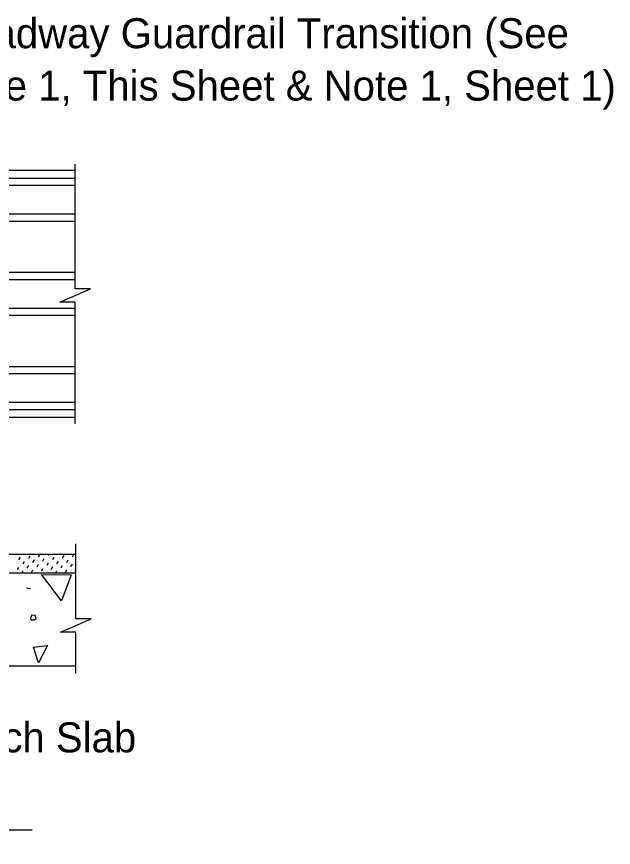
# Model space of a CAD drawing. Extents: x 2.6 to 35.7, y 1.7 to 23.4.
# Drawn here: x 17.6 to 21.61, y 5.94 to 11.53 of the extents above; entities that cross this region are included whole.
import ezdxf

# ---------------------------------------------------------------- set-up
doc = ezdxf.new("R2010")
doc.units = 0
for name, color, linetype in [('Dimension', 7, 'Continuous'), ('Miscellaneous', 7, 'Continuous'), ('TextStructures', 7, 'Continuous'), ('TrafBarrierConc', 7, 'Continuous')]:
    doc.layers.add(name, color=color, linetype=linetype)

msp = doc.modelspace()

# ---------------------------------------------------------------- linework, layer by layer
at = {"layer": 'Dimension'}
for points in [[(17.9936, 8.7897), (17.9936, 9.6071), (17.8903, 9.6071), (17.9936, 9.6521), (18.0969, 9.6971), (17.9936, 9.6971), (17.9936, 10.534)], [(17.9987, 7.1121), (17.9987, 7.389), (17.8953, 7.389), (17.9987, 7.434), (18.102, 7.479), (17.9987, 7.479), (17.9987, 7.9835)], [(17.7044, 6.0586), (14.2297, 6.0586), (14.2297, 5.9424), (14.1304, 6.1674), (14.1304, 6.0586), (12.6311, 6.0586)]]:
    msp.add_lwpolyline(points, dxfattribs=at)
at = {"layer": 'Miscellaneous'}
for p, q in [((10.4769, 10.4934), (17.9962, 10.4934)), ((11.1345, 10.4413), (17.9962, 10.4413)), ((11.1357, 10.393), (17.9962, 10.393)), ((11.1404, 10.2002), (17.9962, 10.2002)), ((11.1416, 10.152), (17.9962, 10.152)), ((11.1381, 9.808), (17.9962, 9.808)), ((11.1369, 9.7598), (17.9962, 9.7598)), ((11.1321, 9.567), (17.9962, 9.567)), ((11.1309, 9.5189), (17.9962, 9.5189)), ((11.1416, 9.1749), (17.9962, 9.1749)), ((11.1404, 9.1267), (17.9962, 9.1267)), ((11.1345, 8.8856), (17.9962, 8.8856)), ((11.1357, 8.9339), (17.9962, 8.9339)), ((10.4769, 8.8333), (17.9962, 8.8333)), ((17.6155, 7.876), (17.6252, 7.8928)), ((17.6818, 7.8857), (17.6915, 7.9025)), ((17.71, 7.8574), (17.7198, 7.8742)), ((17.7481, 7.8954), (17.7578, 7.9122)), ((17.7763, 7.8672), (17.7861, 7.8839)), ((17.8143, 7.9052), (17.8191, 7.9134)), ((17.8426, 7.8769), (17.8524, 7.8937)), ((17.9089, 7.8866), (17.9186, 7.9034)), ((17.9372, 7.8583), (17.9469, 7.8751)), ((17.9752, 7.8963), (17.9849, 7.9131)), ((17.6057, 7.8097), (17.6155, 7.8265)), ((17.6438, 7.8477), (17.6535, 7.8645)), ((17.672, 7.8194), (17.6818, 7.8362)), ((17.7383, 7.8291), (17.7481, 7.8459)), ((17.8046, 7.8389), (17.8143, 7.8557)), ((17.8329, 7.8106), (17.8426, 7.8274)), ((17.8709, 7.8486), (17.8806, 7.8654)), ((17.8992, 7.8203), (17.9089, 7.8371)), ((17.9655, 7.83), (17.9752, 7.8468)), ((17.6381, 7.7884), (17.6438, 7.7982)), ((17.7003, 7.7911), (17.71, 7.8079)), ((17.7666, 7.8009), (17.7763, 7.8177)), ((17.8041, 7.7884), (17.8046, 7.7894)), ((17.8647, 7.7884), (17.8709, 7.7991)), ((17.9275, 7.792), (17.9372, 7.8088)), ((17.9938, 7.8017), (17.9962, 7.8059)), ((17.6671, 7.6867), (17.6936, 7.6814))]:
    msp.add_line(p, q, dxfattribs=at)
for points in [[(17.9022, 7.6), (17.7678, 7.7768), (17.9676, 7.775), (17.9022, 7.6)], [(17.6989, 7.471), (17.7201, 7.471), (17.7307, 7.4816), (17.7254, 7.501), (17.7024, 7.5028), (17.6989, 7.4922), (17.6936, 7.4834), (17.6989, 7.471), (17.6954, 7.4745)], [(17.7466, 7.1828), (17.713, 7.2871), (17.8067, 7.2995), (17.7466, 7.1828)]]:
    msp.add_lwpolyline(points, dxfattribs=at)
at = {"layer": 'TrafBarrierConc'}
for p, q in [((8.4846, 7.9134), (17.9962, 7.9134)), ((8.4846, 7.7884), (17.9962, 7.7884)), ((8.4846, 7.1633), (17.9962, 7.1633))]:
    msp.add_line(p, q, dxfattribs=at)

# ---------------------------------------------------------------- texts
at = {"layer": 'Dimension'}
for s, p in [('Roadway Guardrail Transition (See ', (17.1007, 11.3141)), ('Note 1, This Sheet & Note 1, Sheet 1)', (17.1007, 10.9621))]:
    msp.add_text(s, height=0.2016, dxfattribs=at).set_placement(p)
at = {"layer": 'TextStructures'}
msp.add_text('Existing Approach Slab', height=0.2016, dxfattribs=at).set_placement((15.6162, 6.5811))

doc.saveas('drawing.dxf')
